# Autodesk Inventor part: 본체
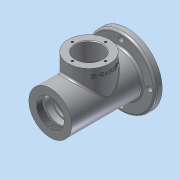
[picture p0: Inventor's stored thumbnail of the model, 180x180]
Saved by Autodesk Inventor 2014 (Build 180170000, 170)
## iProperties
Created: 2016-08
Part Number: 본체
Material: 알루미늄 6061
Document SubType Name: Modeling
Designer: 406-0014
Density: 2.71 g/cm^3
Appearance: 알루미늄 - 평지
Mass: 731.438 g
Surface Area: 616.797 cm^2
Volume: 269.903 cm^3
Author: 406-0014
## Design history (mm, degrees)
sketch "스케치1"
  geometry: C1 r 50 at (0, 0); 1 further point
  constraints: 1 centre point, 1 coincident
  dimensions: "d0" = 100 diameter of C1
extrude "돌출1" new body sketch "스케치1" distance "d1" = 10; taper "d2" = 0 deg
sketch "스케치2"
  geometry: C1 r 50 at (0, 0) reference; C2 r 31 at (0, 0)
  constraints: 1 centre point, 1 coincident
  dimensions: "d3" = 62 diameter of C2
extrude "돌출2" join sketch "스케치2" distance "d4" = 3; taper "d5" = 0 deg
sketch "스케치3"
  geometry: C1 r 50 at (0, 0) reference; C2 r 31 at (0, 0)
  constraints: 1 centre point, 1 coincident
  dimensions: "d6" = 62 diameter of C2
extrude "돌출3" join sketch "스케치3" distance "d7" = 102; taper "d8" = 0 deg
node "작업 평면1"
sketch "스케치4"
  geometry: L1 (-31, -102)-(31, -102) reference; C1 r 30 at (0, -46); 1 further point
  constraints: 1 centre point, 1 vertical alignment
  dimensions: "d10" = 60 diameter of C1; "d11" = 56 distance from line of L1 C1.centre
extrude "돌출4" join sketch "스케치4" stored distance "d12" = 102; taper "d13" = 0 deg
sketch "스케치5"
  geometry: C1 r 31 at (0, 0) reference; C2 r 50 at (0, 0) reference; 1 further point
  constraints: 1 coincident
hole "구멍1" sketch "스케치5" at (0, 0) diameter "d14" = 40.376; stored, may be unused: countersink angle "d18" = 90 deg, drill point angle "d20" = 0 deg; dims "d15" = 9, "d16" = 4, "d17" = 2, "d19" = 9
sketch "스케치6"
  geometry: L1 (0, -102.598)-(0, 13); L2 (-20.188, -93)-(20.188, -93) reference; L3 (0, -93)-(-24, -93); L4 (-24, -93)-(-24, -90); L5 (-24, -90)-(-20, -90); L6 (-20, -90)-(-20, -81); L7 (-20, -81)-(-17.5, -81); L8 (-17.5, -81)-(-17.5, -77.75); L9 (-17.5, -77.75)-(-18.5, -77.75); L10 (-18.5, -77.75)-(-18.5, -76); L11 (-18.5, -76)-(-17.5, -76); L12 (-17.5, -76)-(-17.5, -65); L13 (-17.5, -65)-(-26, -65); L14 (-26, -65)-(-26, -27); L15 (-26, -27)-(0, -27); L16 (20.188, -102)-(-20.188, -102) reference; L17 (-49, -16)-(-49, -76) reference; L18 (0, -93)-(0, -27); 3 further points
  constraints: 30 end point, 7 parallel, 7 perpendicular, 3 midpoint, 1 collinear, 1 horizontal alignment, 1 point on line, 1 vertical, 1 vertical alignment
  dimensions: "d23" = 3 distance between parallel lines of L5 L3; "d24" = 21 distance between parallel lines of L7 L16; "d25" = 1.75 distance between parallel lines of L9 L11; "d26" = 37 diameter of L10 L1; "d27" = 48 diameter of L4 L1; "d28" = 40 diameter of L6 L1; "d29" = 35 diameter of L8 L1; "d30" = 26 distance between parallel lines of L11 L16; "d31" = 35 diameter of L12 L1; "d32" = 52 diameter of L14 L1; "d45" = 38 distance between parallel lines of L15 L13; "d46" = 115.59757 distance of L1.start L1.end
revolve "회전1" sketch "스케치6" stored, may be unused: angle "d47" = 90 deg
sketch "스케치7"
  geometry: L1 (0, 15.236)-(0, -119.929); L2 (-26, -27)-(26, -27) reference; L3 (31, 13)-(-31, 13) reference; L4 (-17.5, -27)-(-17.5, -16.7); L5 (-17.5, -16.7)-(-16.5, -16.7); L6 (-16.5, -16.7)-(-16.5, -11.7); L7 (-16.5, -11.7)-(-10, -11.7); L8 (-10, -11.7)-(-10, -9); L9 (-12.904, -1)-(-16, -1); L10 (-16, -1)-(-21, 13); L11 (-10, -9)-(-12.5, -9); L12 (-12.5, -9)-(-12.5, -1.7); L13 (-12.5, -1.7)-(-12.904, -1); L14 (-17.5, -27)-(0, -27); L15 (-21, 13)-(0, 13); L16 (0, -27)-(0, 13); 1 further point
  constraints: 28 end point, 6 perpendicular, 3 parallel, 2 midpoint, 2 point on line, 1 vertical, 1 vertical alignment
  dimensions: "d48" = 42 diameter of L10.end L1; "d49" = 33 diameter of L6 L1; "d50" = 35 diameter of L4 L1; "d51" = 32 diameter of L9.end L1; "d52" = 30 deg angle of L12 L13; "d53" = 25 diameter of L12 L1; "d54" = 20 diameter of L8 L1; "d55" = 0.7 distance from line of L9 L12.end; "d56" = 14 distance between parallel lines of L3 L9; "d57" = 7.3 distance from line of L11 L12.end; "d58" = 2.7 distance between parallel lines of L11 L7; "d59" = 5 distance between parallel lines of L7 L5; "d60" = 135.16522 distance of L1.start L1.end
revolve "회전2" sketch "스케치7" stored, may be unused: angle "d61" = 90 deg
fillet "모깎기1" dims "d62" = 3
fillet "모깎기2" dims "d63" = 0.3
chamfer "모따기1" distance "d64" = 1; stored, may be unused: second distance "d65" = 2, angle "d66" = 45 deg
fillet "모깎기3" dims "d67" = 3
fillet "모깎기4" dims "d68" = 0.3
sketch "스케치8"
  geometry: C1 r 30 at (0, 0) reference; C2 r 19 at (0, 0); 1 further point
  constraints: 1 centre point, 1 coincident
  dimensions: "d69" = 38 diameter of C2
extrude "돌출5" cut sketch "스케치8" stored distance "d70" = 102; taper "d71" = 0 deg
chamfer "모따기2" distance "d72" = 1; stored, may be unused: second distance "d73" = 2, angle "d74" = 45 deg
sketch "스케치9" dims "d75" = 48
  geometry: C1 r 30 at (0, 0) reference; C2 r 20 at (0, 0) reference; 3 further points
  constraints: 2 vertical alignment, 1 coincident, 2 other
hole "구멍2" sketch "스케치9" at (0, 24) diameter "d76" = 3.242; stored, may be unused: countersink angle "d80" = 90 deg, drill point angle "d82" = 118 deg; dims "d77" = 8, "d78" = 4, "d79" = 2, "d81" = 10
sketch "스케치10" dims "d86" = 83
  geometry: C1 r 31 at (0, 0) reference; C2 r 50 at (0, 0) reference; C3 r 4 at (0, 41.5); 1 further point
  constraints: 2 vertical alignment, 1 centre point, 1 coincident, 2 other
  dimensions: "d87" = 8 diameter of C3
extrude "돌출6" cut sketch "스케치10" stored distance "d88" = 102; taper "d89" = 0 deg
fillet "모깎기5" dims "d93" = 3
fillet "모깎기6" dims "d94" = 3
fillet "모깎기7" dims "d95" = 3
node "작업 평면2"
sketch "스케치11"
  geometry: L1 (-31, -102)-(31, -102) reference; L2 (-49, -16)-(-49, -76) reference; 2 further points
  constraints: 1 other
  dimensions: "d97" = 56 distance from line of L1 point (-39, -46); "d98" = 10 distance from line of L2 point (-39, -46)
feature "엠보싱1" sketch "스케치11" dims "d2" = 0, "d99" = 0.5, "d100" = 0
fillet "모깎기8" dims "d101" = 3
node "솔리드1"
pattern_circular "원형 패턴1" dims angle "d84" = 360 deg
pattern_circular "원형 패턴2" dims angle "d91" = 360 deg
other parameters: "d9" = -49, "d96" = 48.5
